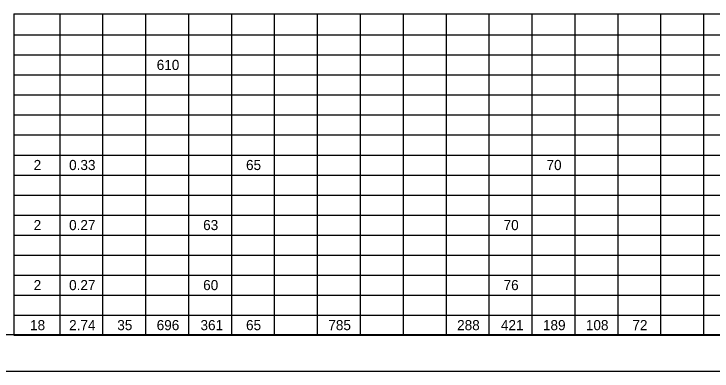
# Model space of a CAD drawing. Extents: x 0.2 to 34.2, y 0 to 22.
# Drawn here: x 14.91 to 24.55, y 0.03 to 4.96 of the extents above; entities that cross this region are included whole.
import ezdxf

# ---------------------------------------------------------------- set-up
doc = ezdxf.new("R2010")
doc.units = 0
for name, color, linetype in [('SH_Border', 7, 'Continuous'), ('SH_Cut_Line', 7, 'Continuous'), ('SH_Text', 7, 'Continuous')]:
    doc.layers.add(name, color=color, linetype=linetype)

msp = doc.modelspace()

# ---------------------------------------------------------------- linework, layer by layer
at = {"layer": 'SH_Border'}
msp.add_lwpolyline([(1.692, 21.5253), (33.692, 21.5253), (33.692, 0.5253), (1.692, 0.5253)], close=True, dxfattribs=at)
at = {"layer": 'SH_Cut_Line'}
msp.add_lwpolyline([(0.192, 0.0253), (34.192, 0.0253), (34.192, 22.0253), (0.192, 22.0253)], close=True, dxfattribs=at)
at = {"layer": 'SH_Text'}
for p, q in [((14.908, 4.9624), (15.5405, 4.9624)), ((14.908, 4.9624), (14.908, 4.6726)), ((15.5405, 4.9624), (24.4346, 4.9624)), ((15.5405, 4.9624), (15.5405, 4.6726)), ((16.1334, 4.9624), (16.1334, 4.6726)), ((16.7264, 4.9624), (16.7264, 4.6726)), ((17.3193, 4.9624), (17.3193, 4.6726)), ((17.9122, 4.9624), (17.9122, 4.6726)), ((18.5052, 4.9624), (18.5052, 4.6726)), ((19.0981, 4.9624), (19.0981, 4.6726)), ((19.6911, 4.9624), (19.6911, 4.6726)), ((20.284, 4.9624), (20.284, 4.6726)), ((20.8769, 4.9624), (20.8769, 4.6726)), ((21.4699, 4.9624), (21.4699, 4.6726)), ((22.0628, 4.9624), (22.0628, 4.6726)), ((22.6558, 4.9624), (22.6558, 4.6726)), ((23.2487, 4.9624), (23.2487, 4.6726)), ((23.8417, 4.9624), (23.8417, 4.6726)), ((24.4346, 4.9624), (32.1955, 4.9624)), ((24.4346, 4.9624), (24.4346, 4.6726)), ((14.908, 4.6726), (15.5405, 4.6726)), ((14.908, 4.6726), (14.908, 4.3958)), ((15.5405, 4.6726), (24.4346, 4.6726)), ((15.5405, 4.6726), (15.5405, 4.3958)), ((16.1334, 4.6726), (16.1334, 4.3958)), ((16.7264, 4.6726), (16.7264, 4.3958)), ((17.3193, 4.6726), (17.3193, 4.3958)), ((17.9122, 4.6726), (17.9122, 4.3958)), ((18.5052, 4.6726), (18.5052, 4.3958)), ((19.0981, 4.6726), (19.0981, 4.3958)), ((19.6911, 4.6726), (19.6911, 4.3958)), ((20.284, 4.6726), (20.284, 4.3958)), ((20.8769, 4.6726), (20.8769, 4.3958)), ((21.4699, 4.6726), (21.4699, 4.3958)), ((22.0628, 4.6726), (22.0628, 4.3958)), ((22.6558, 4.6726), (22.6558, 4.3958)), ((23.2487, 4.6726), (23.2487, 4.3958)), ((23.8417, 4.6726), (23.8417, 4.3958)), ((24.4346, 4.6726), (32.1955, 4.6726)), ((24.4346, 4.6726), (24.4346, 4.3958)), ((14.908, 4.3958), (15.5405, 4.3958)), ((14.908, 4.3958), (14.908, 4.1191)), ((15.5405, 4.3958), (24.4346, 4.3958)), ((15.5405, 4.3958), (15.5405, 4.1191)), ((16.1334, 4.3958), (16.1334, 4.1191)), ((16.7264, 4.3958), (16.7264, 4.1191)), ((17.3193, 4.3958), (17.3193, 4.1191)), ((17.9122, 4.3958), (17.9122, 4.1191)), ((18.5052, 4.3958), (18.5052, 4.1191)), ((19.0981, 4.3958), (19.0981, 4.1191)), ((19.6911, 4.3958), (19.6911, 4.1191)), ((20.284, 4.3958), (20.284, 4.1191)), ((20.8769, 4.3958), (20.8769, 4.1191)), ((21.4699, 4.3958), (21.4699, 4.1191)), ((22.0628, 4.3958), (22.0628, 4.1191)), ((22.6558, 4.3958), (22.6558, 4.1191)), ((23.2487, 4.3958), (23.2487, 4.1191)), ((23.8417, 4.3958), (23.8417, 4.1191)), ((24.4346, 4.3958), (32.1955, 4.3958)), ((24.4346, 4.3958), (24.4346, 4.1191)), ((14.908, 4.1191), (15.5405, 4.1191)), ((14.908, 4.1191), (14.908, 3.8424)), ((15.5405, 4.1191), (24.4346, 4.1191)), ((15.5405, 4.1191), (15.5405, 3.8424)), ((16.1334, 4.1191), (16.1334, 3.8424)), ((16.7264, 4.1191), (16.7264, 3.8424)), ((17.3193, 4.1191), (17.3193, 3.8424)), ((17.9122, 4.1191), (17.9122, 3.8424)), ((18.5052, 4.1191), (18.5052, 3.8424)), ((19.0981, 4.1191), (19.0981, 3.8424)), ((19.6911, 4.1191), (19.6911, 3.8424)), ((20.284, 4.1191), (20.284, 3.8424)), ((20.8769, 4.1191), (20.8769, 3.8424)), ((21.4699, 4.1191), (21.4699, 3.8424)), ((22.0628, 4.1191), (22.0628, 3.8424)), ((22.6558, 4.1191), (22.6558, 3.8424)), ((23.2487, 4.1191), (23.2487, 3.8424)), ((23.8417, 4.1191), (23.8417, 3.8424)), ((24.4346, 4.1191), (32.1955, 4.1191)), ((24.4346, 4.1191), (24.4346, 3.8424)), ((14.908, 3.8424), (15.5405, 3.8424)), ((14.908, 3.8424), (14.908, 3.289)), ((15.5405, 3.8424), (24.4346, 3.8424)), ((15.5405, 3.8424), (15.5405, 3.289)), ((16.1334, 3.8424), (16.1334, 3.289)), ((16.7264, 3.8424), (16.7264, 3.289)), ((17.3193, 3.8424), (17.3193, 3.289)), ((17.9122, 3.8424), (17.9122, 3.289)), ((18.5052, 3.8424), (18.5052, 3.289)), ((19.0981, 3.8424), (19.0981, 3.289)), ((19.6911, 3.8424), (19.6911, 3.289)), ((20.284, 3.8424), (20.284, 3.289)), ((20.8769, 3.8424), (20.8769, 3.289)), ((21.4699, 3.8424), (21.4699, 3.289)), ((22.0628, 3.8424), (22.0628, 3.289)), ((22.6558, 3.8424), (22.6558, 3.289)), ((23.2487, 3.8424), (23.2487, 3.289)), ((23.8417, 3.8424), (23.8417, 3.289)), ((24.4346, 3.8424), (32.1955, 3.8424)), ((24.4346, 3.8424), (24.4346, 3.289)), ((14.908, 3.5657), (15.5405, 3.5657)), ((15.5405, 3.5657), (24.4346, 3.5657)), ((24.4346, 3.5657), (32.1955, 3.5657)), ((14.908, 3.289), (15.5405, 3.289)), ((14.908, 3.289), (14.908, 3.0123)), ((15.5405, 3.289), (24.4346, 3.289)), ((15.5405, 3.289), (15.5405, 3.0123)), ((16.1334, 3.289), (16.1334, 3.0123)), ((16.7264, 3.289), (16.7264, 3.0123)), ((17.3193, 3.289), (17.3193, 3.0123)), ((17.9122, 3.289), (17.9122, 3.0123)), ((18.5052, 3.289), (18.5052, 3.0123)), ((19.0981, 3.289), (19.0981, 3.0123)), ((19.6911, 3.289), (19.6911, 3.0123)), ((20.284, 3.289), (20.284, 3.0123)), ((20.8769, 3.289), (20.8769, 3.0123)), ((21.4699, 3.289), (21.4699, 3.0123)), ((22.0628, 3.289), (22.0628, 3.0123)), ((22.6558, 3.289), (22.6558, 3.0123)), ((23.2487, 3.289), (23.2487, 3.0123)), ((23.8417, 3.289), (23.8417, 3.0123)), ((24.4346, 3.289), (32.1955, 3.289)), ((24.4346, 3.289), (24.4346, 3.0123)), ((14.908, 3.0123), (15.5405, 3.0123)), ((14.908, 3.0123), (14.908, 2.7356)), ((15.5405, 3.0123), (24.4346, 3.0123)), ((15.5405, 3.0123), (15.5405, 2.7356)), ((16.1334, 3.0123), (16.1334, 2.7356)), ((16.7264, 3.0123), (16.7264, 2.7356)), ((17.3193, 3.0123), (17.3193, 2.7356)), ((17.9122, 3.0123), (17.9122, 2.7356)), ((18.5052, 3.0123), (18.5052, 2.7356)), ((19.0981, 3.0123), (19.0981, 2.7356)), ((19.6911, 3.0123), (19.6911, 2.7356)), ((20.284, 3.0123), (20.284, 2.7356)), ((20.8769, 3.0123), (20.8769, 2.7356)), ((21.4699, 3.0123), (21.4699, 2.7356)), ((22.0628, 3.0123), (22.0628, 2.7356)), ((22.6558, 3.0123), (22.6558, 2.7356)), ((23.2487, 3.0123), (23.2487, 2.7356)), ((23.8417, 3.0123), (23.8417, 2.7356)), ((24.4346, 3.0123), (32.1955, 3.0123)), ((24.4346, 3.0123), (24.4346, 2.7356)), ((14.908, 2.7356), (15.5405, 2.7356)), ((14.908, 2.7356), (14.908, 2.4589)), ((15.5405, 2.7356), (24.4346, 2.7356)), ((15.5405, 2.7356), (15.5405, 2.4589)), ((16.1334, 2.7356), (16.1334, 2.4589)), ((16.7264, 2.7356), (16.7264, 2.4589)), ((17.3193, 2.7356), (17.3193, 2.4589)), ((17.9122, 2.7356), (17.9122, 2.4589)), ((18.5052, 2.7356), (18.5052, 2.4589)), ((19.0981, 2.7356), (19.0981, 2.4589)), ((19.6911, 2.7356), (19.6911, 2.4589)), ((20.284, 2.7356), (20.284, 2.4589)), ((20.8769, 2.7356), (20.8769, 2.4589)), ((21.4699, 2.7356), (21.4699, 2.4589)), ((22.0628, 2.7356), (22.0628, 2.4589)), ((22.6558, 2.7356), (22.6558, 2.4589)), ((23.2487, 2.7356), (23.2487, 2.4589)), ((23.8417, 2.7356), (23.8417, 2.4589)), ((24.4346, 2.7356), (32.1955, 2.7356)), ((24.4346, 2.7356), (24.4346, 2.4589)), ((14.908, 2.4589), (15.5405, 2.4589)), ((14.908, 2.4589), (14.908, 1.9055)), ((15.5405, 2.4589), (24.4346, 2.4589)), ((15.5405, 2.4589), (15.5405, 1.9055)), ((16.1334, 2.4589), (16.1334, 1.9055)), ((16.7264, 2.4589), (16.7264, 1.9055)), ((17.3193, 2.4589), (17.3193, 1.9055)), ((17.9122, 2.4589), (17.9122, 1.9055)), ((18.5052, 2.4589), (18.5052, 1.9055)), ((19.0981, 2.4589), (19.0981, 1.9055)), ((19.6911, 2.4589), (19.6911, 1.9055)), ((20.284, 2.4589), (20.284, 1.9055)), ((20.8769, 2.4589), (20.8769, 1.9055)), ((21.4699, 2.4589), (21.4699, 1.9055)), ((22.0628, 2.4589), (22.0628, 1.9055)), ((22.6558, 2.4589), (22.6558, 1.9055)), ((23.2487, 2.4589), (23.2487, 1.9055)), ((23.8417, 2.4589), (23.8417, 1.9055)), ((24.4346, 2.4589), (32.1955, 2.4589)), ((24.4346, 2.4589), (24.4346, 1.9055)), ((14.908, 2.1822), (15.5405, 2.1822)), ((15.5405, 2.1822), (24.4346, 2.1822)), ((24.4346, 2.1822), (32.1955, 2.1822)), ((14.908, 1.9055), (15.5405, 1.9055)), ((14.908, 1.9055), (14.908, 1.6288)), ((15.5405, 1.9055), (24.4346, 1.9055)), ((15.5405, 1.9055), (15.5405, 1.6288)), ((16.1334, 1.9055), (16.1334, 1.6288)), ((16.7264, 1.9055), (16.7264, 1.6288)), ((17.3193, 1.9055), (17.3193, 1.6288)), ((17.9122, 1.9055), (17.9122, 1.6288)), ((18.5052, 1.9055), (18.5052, 1.6288)), ((19.0981, 1.9055), (19.0981, 1.6288)), ((19.6911, 1.9055), (19.6911, 1.6288)), ((20.284, 1.9055), (20.284, 1.6288)), ((20.8769, 1.9055), (20.8769, 1.6288)), ((21.4699, 1.9055), (21.4699, 1.6288)), ((22.0628, 1.9055), (22.0628, 1.6288)), ((22.6558, 1.9055), (22.6558, 1.6288)), ((23.2487, 1.9055), (23.2487, 1.6288)), ((23.8417, 1.9055), (23.8417, 1.6288)), ((24.4346, 1.9055), (32.1955, 1.9055)), ((24.4346, 1.9055), (24.4346, 1.6288)), ((14.908, 1.6288), (15.5405, 1.6288)), ((14.908, 1.6288), (14.908, 1.3521)), ((15.5405, 1.6288), (24.4346, 1.6288)), ((15.5405, 1.6288), (15.5405, 1.3521)), ((16.1334, 1.6288), (16.1334, 1.3521)), ((16.7264, 1.6288), (16.7264, 1.3521)), ((17.3193, 1.6288), (17.3193, 1.3521)), ((17.9122, 1.6288), (17.9122, 1.3521)), ((18.5052, 1.6288), (18.5052, 1.3521)), ((19.0981, 1.6288), (19.0981, 1.3521)), ((19.6911, 1.6288), (19.6911, 1.3521)), ((20.284, 1.6288), (20.284, 1.3521)), ((20.8769, 1.6288), (20.8769, 1.3521)), ((21.4699, 1.6288), (21.4699, 1.3521)), ((22.0628, 1.6288), (22.0628, 1.3521)), ((22.6558, 1.6288), (22.6558, 1.3521)), ((23.2487, 1.6288), (23.2487, 1.3521)), ((23.8417, 1.6288), (23.8417, 1.3521)), ((24.4346, 1.6288), (32.1955, 1.6288)), ((24.4346, 1.6288), (24.4346, 1.3521)), ((14.908, 1.3521), (15.5405, 1.3521)), ((14.908, 1.3521), (14.908, 1.0754)), ((15.5405, 1.3521), (24.4346, 1.3521)), ((15.5405, 1.3521), (15.5405, 1.0754)), ((16.1334, 1.3521), (16.1334, 1.0754)), ((16.7264, 1.3521), (16.7264, 1.0754)), ((17.3193, 1.3521), (17.3193, 1.0754)), ((17.9122, 1.3521), (17.9122, 1.0754)), ((18.5052, 1.3521), (18.5052, 1.0754)), ((19.0981, 1.3521), (19.0981, 1.0754)), ((19.6911, 1.3521), (19.6911, 1.0754)), ((20.284, 1.3521), (20.284, 1.0754)), ((20.8769, 1.3521), (20.8769, 1.0754)), ((21.4699, 1.3521), (21.4699, 1.0754)), ((22.0628, 1.3521), (22.0628, 1.0754)), ((22.6558, 1.3521), (22.6558, 1.0754)), ((23.2487, 1.3521), (23.2487, 1.0754)), ((23.8417, 1.3521), (23.8417, 1.0754)), ((24.4346, 1.3521), (32.1955, 1.3521)), ((24.4346, 1.3521), (24.4346, 1.0754)), ((14.908, 1.0754), (15.5405, 1.0754)), ((14.908, 1.0754), (14.908, 0.522)), ((15.5405, 1.0754), (24.4346, 1.0754)), ((15.5405, 1.0754), (15.5405, 0.522)), ((16.1334, 1.0754), (16.1334, 0.522)), ((16.7264, 1.0754), (16.7264, 0.522)), ((17.3193, 1.0754), (17.3193, 0.522)), ((17.9122, 1.0754), (17.9122, 0.522)), ((18.5052, 1.0754), (18.5052, 0.522)), ((19.0981, 1.0754), (19.0981, 0.522)), ((19.6911, 1.0754), (19.6911, 0.522)), ((20.284, 1.0754), (20.284, 0.522)), ((20.8769, 1.0754), (20.8769, 0.522)), ((21.4699, 1.0754), (21.4699, 0.522)), ((22.0628, 1.0754), (22.0628, 0.522)), ((22.6558, 1.0754), (22.6558, 0.522)), ((23.2487, 1.0754), (23.2487, 0.522)), ((23.8417, 1.0754), (23.8417, 0.522)), ((24.4346, 1.0754), (32.1955, 1.0754)), ((24.4346, 1.0754), (24.4346, 0.522)), ((14.908, 0.7987), (15.5405, 0.7987)), ((15.5405, 0.7987), (24.4346, 0.7987)), ((24.4346, 0.7987), (32.1955, 0.7987)), ((14.908, 0.522), (15.5405, 0.522)), ((15.5405, 0.522), (24.4346, 0.522)), ((24.4346, 0.522), (32.1955, 0.522))]:
    msp.add_line(p, q, dxfattribs=at)

# ---------------------------------------------------------------- texts
for s, p in [('610', (16.8803, 4.1875)), ('2', (15.18, 2.804)), ('0.33', (15.6697, 2.804)), ('65', (18.1144, 2.804)), ('70', (22.2657, 2.804)), ('2', (15.18, 1.9738)), ('0.27', (15.6697, 1.9738)), ('63', (17.5219, 1.9738)), ('70', (21.6727, 1.9738)), ('2', (15.18, 1.1437)), ('0.27', (15.6697, 1.1437)), ('60', (17.5221, 1.1437)), ('76', (21.6725, 1.1437)), ('18', (15.1303, 0.5903)), ('2.74', (15.67, 0.5903)), ('35', (16.3355, 0.5903)), ('696', (16.88, 0.5903)), ('361', (17.4852, 0.5903)), ('65', (18.1144, 0.5903)), ('785', (19.2513, 0.5903)), ('288', (21.0305, 0.5903)), ('421', (21.6357, 0.5903)), ('189', (22.2164, 0.5903)), ('108', (22.8093, 0.5903)), ('72', (23.452, 0.5903))]:
    msp.add_text(s, height=0.14, dxfattribs=at).set_placement(p)

doc.saveas('drawing.dxf')
